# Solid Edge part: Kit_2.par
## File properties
Sűrűség: 0,000 kg/m^3
Pontosság: 0,990
Author: ahadarics
Last saved by: psaghy
Revision: 77
Username: ahadarics
Dokumentum tartalom típus: 0
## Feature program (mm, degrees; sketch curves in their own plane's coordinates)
base feature "unnamed BaseFeature 1"
sketch for "Furat_1" plane through (0, 0, 32.5) normal (0, 0, 1) x-axis (0, -1, 0)
  hole centre (-16.25, 16.25) bore radius 2.4585
hole "Furat_1" nominal diameter 6 finite  VBottomAngle = 118 deg; ThreadDepth = 16 mm
sketch for "unnamed Hole 1" plane through (0, 0, 32.5) normal (0, 0, 1) x-axis (0, -1, 0)
  hole centre (-16.25, -16.25) bore radius 2.4585
hole "unnamed Hole 1" finite
sketch for "unnamed Hole 2" plane through (0, 0, 32.5) normal (0, 0, 1) x-axis (0, -1, 0)
  hole centre (16.25, -16.25) bore radius 2.4585
hole "unnamed Hole 2" finite
sketch for "unnamed Hole 3" plane through (0, 0, 32.5) normal (0, 0, 1) x-axis (0, -1, 0)
  hole centre (16.25, 16.25) bore radius 2.4585
hole "unnamed Hole 3" finite
pattern "unnamed Pattern 1" of "Furat_1", "unnamed Hole 1", "unnamed Hole 2", "unnamed Hole 3"
sketch for "Furat_5" plane through (23.5, 0.0133, 16.7488) normal (1, 0, 0) x-axis (0, 0, -1)
hole "Furat_5" diameter 9.728 finite  ThreadDepth = 9 mm
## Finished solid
Body 1: solid body, 384 faces, 920 edges, 589 vertices, 3 internal voids.
  Faces by surface: cylinder 131, plane 125, cone 46, torus 39, spline 31, sphere 10, swept 2
  Edges by curve: circle 312, curve on surface 296, line 296, spline 16
Bounding box of the edges (mm; curved faces can reach further): 47.001 x 47.000 x 44.500, from (-23.5, -23.5, 6) to (23.5005, 23.5, 50.5).
Cylindrical faces by radius (mm): R0.2287 x1, R0.2297 x1, R0.2305 x1, R0.232 x1, R0.2354 x1, R0.2616 x1, R0.2684 x1, R0.2696 x1, R0.274 x1, R0.2809 x1, R0.2869 x1, R0.2897 x2, R0.2949 x1, R0.2975 x1, R0.2999 x1, R0.3047 x1, R0.3049 x1, R0.3054 x1, R0.3191 x1, R0.3251 x1, R0.3471 x1, R0.361 x1, R0.3789 x1, R0.3925 x1, R0.3994 x1, R0.4078 x1, R0.4206 x1, R0.4339 x1, R0.4364 x1, R0.4536 x1, R0.4559 x1, R0.4564 x1, R0.4771 x1, R0.4781 x1, R0.5 x7, R0.5094 x1, R0.5174 x1, R0.5354 x1, R0.5534 x1, R0.6836 x1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
Conical faces (half-angle, radius in mm at the cone's reference point): 1.6538 deg R7.75 x1, 3.5477 deg R8.7454 x1, 5.1549 deg R0.4847 x1, 5.762 deg R6.4 x1, 11.1239 deg R6.0056 x1, 15 deg R13.6406 x1, 15.3654 deg R6.7214 x1, 19.3654 deg R7.1921 x1, 25.0169 deg R10.31 x1, 27.5528 deg R20.5 x4, 30 deg R4.0866 x1, 30 deg R7.8557 x2, 30 deg R8.1443 x1, 30 deg R14.5 x1, 45 deg R1.1 x1, 45 deg R2.3 x1, 45 deg R2.4 x1, 45 deg R3.25 x8, 45 deg R4.85 x8, 45 deg R5.18 x1, 45 deg R6.15 x2, 45 deg R11.25 x1, 59 deg R1.75 x1, 59 deg R2.4585 x4
Toroidal faces (ring radius, tube radius in mm): R0.7228 r0.5 x1, R0.8364 r0.5 x1, R1.4663 r0.5006 x3, R3.3 r0.3 x4, R3.6 r0.4 x1, R3.7 r0.3 x1, R4.95 r0.2 x4, R5.65 r0.5 x4, R6.3 r0.3 x1, R6.3085 r0.3 x1, R7.4279 r0.25 x1, R7.75 r0.5 x1, R8 r0.5 x1, R8.2464 r0.5 x1, R10.8 r0.2 x1, R12 r2 x1, R12.8663 r0.5 x1, R15.5 r0.5 x1, R18 r1 x3, R22.5 r1 x6, R23.8031 r0.5 x1
Spherical faces by radius (mm): R0.5 x4, R1 x6
Planar faces by outward normal: +x 19, +y 9, +z 29, -x 2, -y 9, -z 17, oblique 40
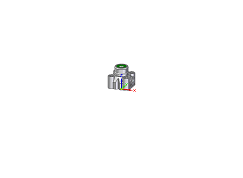
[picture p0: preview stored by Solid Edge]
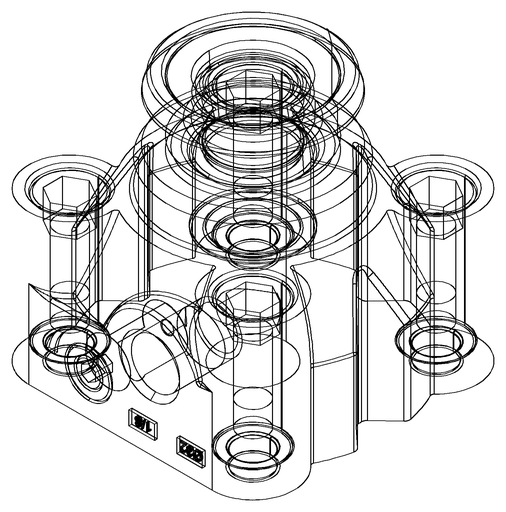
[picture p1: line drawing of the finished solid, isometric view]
